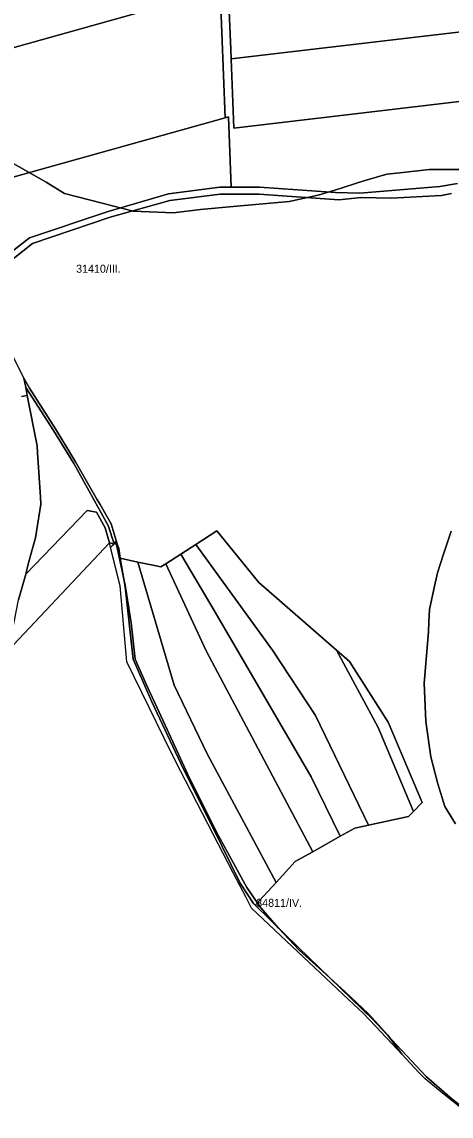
# Model space of a CAD drawing. Extents: x -541351 to -537540, y -1162694 to -1159725.
# Drawn here: x -539137 to -538870, y -1162618 to -1161934 of the extents above; entities that cross this region are included whole.
import ezdxf

# ---------------------------------------------------------------- set-up
doc = ezdxf.new("R2010")
doc.units = 0
for name, color, linetype in [('95560013', 7, 'Continuous'), ('95640013', 7, 'Continuous'), ('95660013', 7, 'Continuous')]:
    doc.layers.add(name, color=color, linetype=linetype)

msp = doc.modelspace()

# ---------------------------------------------------------------- linework, layer by layer
at = {"layer": '95560013'}
for points in [[(-539212.32, -1161913.69), (-539214.84, -1161903.7), (-539217.45, -1161893.33), (-539017.01, -1161837.1), (-539013.85, -1161913.55), (-539200.6, -1161966.02), (-539206.22, -1161940.94)], [(-539007.14, -1161951.05), (-539008.79, -1161912.59), (-538817.52, -1161890.24), (-538820.83, -1161934.92), (-539006.92, -1161956.95)], [(-539197.76, -1161978.7), (-539200.6, -1161966.02), (-539013.85, -1161913.55), (-539010.53, -1161993.75), (-539184.9, -1162042.56), (-539186.67, -1162034.94), (-539187.18, -1162032.19), (-539193.59, -1161997.34)], [(-538820.83, -1161934.92), (-538824.09, -1161978.8), (-539005.3, -1162000.22), (-539006.92, -1161956.95)], [(-539083.65, -1162052.18), (-539132.72, -1162068.62), (-539167.17, -1162095.62), (-539177.1, -1162076.06), (-539179.07, -1162067.59), (-539184.9, -1162042.56), (-539010.53, -1161993.75), (-539008.56, -1161993.2), (-539006.92, -1162037.12), (-539013.92, -1162037.13), (-539045.95, -1162041.27)], [(-539128.98, -1162256.1), (-539125.58, -1162235.11), (-539125.86, -1162230.82), (-539127.7, -1162203.08), (-539127.98, -1162198.77), (-539134.14, -1162167.31), (-539135.1, -1162162.18), (-539117.68, -1162189.14), (-539105.17, -1162209.73), (-539083.56, -1162248.52), (-539080, -1162259.98), (-539082.83, -1162259.23), (-539085.53, -1162249.94), (-539091, -1162240.09), (-539096.84, -1162239.12), (-539135.12, -1162278.84), (-539133.55, -1162272.74), (-539131.26, -1162264.39)], [(-539139.62, -1162294.87), (-539135.12, -1162278.84), (-539096.84, -1162239.12), (-539091, -1162240.09), (-539085.53, -1162249.94), (-539082.83, -1162259.23), (-539142.64, -1162323.16), (-539145.63, -1162326.35), (-539145.6, -1162326.2)], [(-538921.23, -1162435.74), (-538954.32, -1162367.32), (-538981.04, -1162326.43), (-539028.88, -1162260.3), (-539015.79, -1162251.87), (-538989.69, -1162284.09), (-538941.12, -1162326.35), (-538915.25, -1162374.75), (-538893.18, -1162427.24), (-538896.24, -1162430.37)], [(-538929.69, -1162437.56), (-538938.83, -1162442.7), (-538956.93, -1162405.55), (-539016.81, -1162302.57), (-539038.32, -1162266.38), (-539028.88, -1162260.3), (-538981.04, -1162326.43), (-538954.32, -1162367.32), (-538921.23, -1162435.74)], [(-539056.46, -1162358.75), (-539068.09, -1162332.03), (-539073.03, -1162286.84), (-539076.06, -1162268.99), (-539065.09, -1162271.35), (-539042.53, -1162348.19), (-539021.89, -1162391.27), (-538978.82, -1162471.52), (-538991.83, -1162485.79), (-538992.91, -1162484.72), (-539001.22, -1162471.94), (-539018.06, -1162437.54), (-539036.61, -1162400.8)], [(-538956.01, -1162452.36), (-538965.48, -1162457.69), (-538966.96, -1162458.52), (-538978.82, -1162471.52), (-539021.89, -1162391.27), (-539042.53, -1162348.19), (-539065.09, -1162271.35), (-539053.73, -1162273.79), (-539050.8, -1162274.41), (-539047.58, -1162272.35), (-539022.54, -1162326.91)], [(-539016.81, -1162302.57), (-538956.93, -1162405.55), (-538938.83, -1162442.7), (-538956.01, -1162452.36), (-539022.54, -1162326.91), (-539047.58, -1162272.35), (-539038.32, -1162266.38)], [(-538941.12, -1162326.35), (-538932.97, -1162333.44), (-538908.81, -1162371.47), (-538887.63, -1162421.53), (-538893.18, -1162427.24), (-538915.25, -1162374.75)]]:
    msp.add_lwpolyline(points, close=True, dxfattribs=at)
for points in [[(-538865.57, -1162034.76), (-538876.72, -1162036.74), (-538926.62, -1162040.85), (-538941.77, -1162040.48), (-538989.17, -1162037.11), (-539003.92, -1162037.12), (-539006.92, -1162037.12), (-539008.56, -1161993.2), (-539010.53, -1161993.75), (-539013.85, -1161913.55)], [(-539008.79, -1161912.59), (-539007.14, -1161951.05), (-539006.92, -1161956.95), (-539005.3, -1162000.22), (-538824.09, -1161978.8)], [(-539165.27, -1162099.36), (-539130.8, -1162072.28), (-539082.49, -1162055.78), (-539045.11, -1162045.4), (-539013.66, -1162041.4), (-538989.46, -1162041.38), (-538939.77, -1162044.97), (-538925.8, -1162043.6), (-538907.04, -1162043.97), (-538875.54, -1162042.25), (-538869.43, -1162041.03)], [(-538855.65, -1162617.58), (-538870.45, -1162605.67), (-538885.13, -1162592.83), (-538918.63, -1162556.93), (-538964.98, -1162512.08), (-538991.83, -1162485.79), (-538978.82, -1162471.52), (-538966.96, -1162458.52), (-538965.48, -1162457.69), (-538956.01, -1162452.36), (-538938.83, -1162442.7), (-538929.69, -1162437.56), (-538921.23, -1162435.74), (-538896.24, -1162430.37), (-538893.18, -1162427.24), (-538887.63, -1162421.53), (-538908.81, -1162371.47), (-538932.97, -1162333.44), (-538941.12, -1162326.35), (-538989.69, -1162284.09), (-539015.79, -1162251.87), (-539028.88, -1162260.3), (-539038.32, -1162266.38), (-539047.58, -1162272.35), (-539050.8, -1162274.41), (-539053.73, -1162273.79), (-539065.09, -1162271.35), (-539076.06, -1162268.99), (-539077.08, -1162262.94), (-539077.99, -1162260.02), (-539081.84, -1162247.4), (-539088.7, -1162235.39), (-539090.65, -1162231.98), (-539103.97, -1162208.68), (-539116.44, -1162188.05), (-539132.79, -1162162.66), (-539136.3, -1162156.43), (-539142.82, -1162143.59)]]:
    msp.add_lwpolyline(points, dxfattribs=at)
at = {"layer": '95640013'}
for points in [[(-538869.43, -1162041.03), (-538875.54, -1162042.25), (-538907.04, -1162043.97), (-538925.8, -1162043.6), (-538939.77, -1162044.97), (-538989.46, -1162041.38), (-539013.66, -1162041.4), (-539045.11, -1162045.4), (-539082.49, -1162055.78), (-539130.8, -1162072.28), (-539165.27, -1162099.36), (-539167.17, -1162095.62), (-539132.72, -1162068.62), (-539083.65, -1162052.18), (-539045.95, -1162041.27), (-539013.92, -1162037.13), (-539006.92, -1162037.12), (-539003.92, -1162037.12), (-538989.17, -1162037.11), (-538941.77, -1162040.48), (-538926.62, -1162040.85), (-538876.72, -1162036.74), (-538865.57, -1162034.76)], [(-539142.82, -1162143.59), (-539136.3, -1162156.43), (-539135.1, -1162162.18), (-539134.14, -1162167.31), (-539137.66, -1162167.95)], [(-539137.66, -1162167.95), (-539134.14, -1162167.31), (-539127.98, -1162198.77), (-539127.7, -1162203.08), (-539125.86, -1162230.82), (-539125.58, -1162235.11), (-539128.98, -1162256.1), (-539131.26, -1162264.39), (-539133.55, -1162272.74), (-539135.12, -1162278.84), (-539139.62, -1162294.87)], [(-538862.99, -1162612.9), (-538874.92, -1162603.19), (-538885.86, -1162594.28), (-538889.69, -1162590.22), (-538903.28, -1162575.82), (-538916.9, -1162561.39), (-538924.5, -1162553.34), (-538927.27, -1162550.73), (-538937.03, -1162541.53), (-538979.54, -1162501.45), (-538994.17, -1162487.65), (-538997.62, -1162480.98), (-539005.64, -1162465.5), (-539015.03, -1162447.36), (-539024.84, -1162428.38), (-539035.48, -1162407.82), (-539038.4, -1162402.18), (-539044.02, -1162390.7), (-539071.91, -1162333.79), (-539076.15, -1162286.28), (-539082.83, -1162259.23), (-539080, -1162259.98), (-539077.99, -1162260.02), (-539077.08, -1162262.94), (-539076.06, -1162268.99), (-539073.03, -1162286.84), (-539068.09, -1162332.03), (-539056.46, -1162358.75), (-539036.61, -1162400.8), (-539018.06, -1162437.54), (-539001.22, -1162471.94), (-538992.91, -1162484.72), (-538991.83, -1162485.79), (-538964.98, -1162512.08), (-538918.63, -1162556.93), (-538885.13, -1162592.83), (-538870.45, -1162605.67), (-538855.65, -1162617.58)]]:
    msp.add_lwpolyline(points, dxfattribs=at)
msp.add_lwpolyline([(-539136.3, -1162156.43), (-539132.79, -1162162.66), (-539116.44, -1162188.05), (-539103.97, -1162208.68), (-539090.65, -1162231.98), (-539088.7, -1162235.39), (-539081.84, -1162247.4), (-539077.99, -1162260.02), (-539080, -1162259.98), (-539083.56, -1162248.52), (-539105.17, -1162209.73), (-539117.68, -1162189.14), (-539135.1, -1162162.18)], close=True, dxfattribs=at)
at = {"layer": '95660013'}
for points in [[(-538849.37, -1162026), (-538883.31, -1162026), (-538901.69, -1162028), (-538909.81, -1162029), (-538924.12, -1162033), (-538942.12, -1162039), (-538952.69, -1162042), (-538970.62, -1162046), (-539003.31, -1162049), (-539026, -1162051), (-539042.81, -1162053), (-539068, -1162052), (-539087.37, -1162047), (-539110.81, -1162041), (-539122.37, -1162034), (-539146.81, -1162020), (-539161.87, -1162007), (-539166.31, -1162000), (-539179.62, -1161966), (-539195.31, -1161920)], [(-539195.31, -1161920), (-539179.62, -1161966), (-539166.31, -1162000), (-539161.87, -1162007), (-539146.81, -1162020), (-539122.37, -1162034), (-539110.81, -1162041), (-539087.37, -1162047), (-539068, -1162052), (-539042.81, -1162053), (-539026, -1162051), (-539003.31, -1162049), (-538970.62, -1162046), (-538952.69, -1162042), (-538942.12, -1162039), (-538924.12, -1162033), (-538909.81, -1162029), (-538901.69, -1162028), (-538883.31, -1162026), (-538849.37, -1162026)], [(-538866.81, -1162435), (-538873.5, -1162424), (-538877.87, -1162410), (-538882.31, -1162393), (-538885.37, -1162371), (-538886.5, -1162347), (-538883.69, -1162315), (-538883.44, -1162308.78), (-538883.12, -1162301), (-538880.38, -1162288.22), (-538878.19, -1162278), (-538874.38, -1162266.44), (-538869.62, -1162252)], [(-538869.62, -1162252), (-538874.38, -1162266.44), (-538878.19, -1162278), (-538880.38, -1162288.22), (-538883.12, -1162301), (-538883.44, -1162308.78), (-538883.69, -1162315), (-538886.5, -1162347), (-538885.37, -1162371), (-538882.31, -1162393), (-538877.87, -1162410), (-538873.5, -1162424), (-538866.81, -1162435)], [(-538862.99, -1162612.9), (-538874.92, -1162603.19), (-538885.86, -1162594.28), (-538889.69, -1162590.22), (-538900.42, -1162578.85), (-538909.05, -1162566.98), (-538921.18, -1162553.62), (-538935.8, -1162539.98), (-538949.84, -1162527.04), (-538964.37, -1162513.81), (-538977.37, -1162500.12), (-538988.32, -1162487.46), (-538997.13, -1162474.77), (-539014.94, -1162441.97), (-539033.92, -1162404.18), (-539048.17, -1162373.22), (-539059.88, -1162347.62), (-539066.83, -1162331.98), (-539069.27, -1162309.34), (-539072.95, -1162285.74), (-539078.86, -1162258.5), (-539081.02, -1162260.99), (-539081.75, -1162261.77), (-539082.11, -1162262.15), (-539082.83, -1162259.23), (-539142.64, -1162323.16)]]:
    msp.add_lwpolyline(points, dxfattribs=at)
msp.add_lwpolyline([(-538909.05, -1162566.98), (-538900.42, -1162578.85), (-538903.28, -1162575.82), (-538916.9, -1162561.39), (-538924.5, -1162553.34), (-538927.27, -1162550.73), (-538937.03, -1162541.53), (-538979.54, -1162501.45), (-538994.17, -1162487.65), (-538997.62, -1162480.98), (-539005.64, -1162465.5), (-539015.03, -1162447.36), (-539024.84, -1162428.38), (-539035.48, -1162407.82), (-539038.4, -1162402.18), (-539044.02, -1162390.7), (-539071.91, -1162333.79), (-539076.15, -1162286.28), (-539082.11, -1162262.15), (-539081.75, -1162261.77), (-539081.02, -1162260.99), (-539078.86, -1162258.5), (-539072.95, -1162285.74), (-539069.27, -1162309.34), (-539066.83, -1162331.98), (-539059.88, -1162347.62), (-539048.17, -1162373.22), (-539033.92, -1162404.18), (-539014.94, -1162441.97), (-538997.13, -1162474.77), (-538988.32, -1162487.46), (-538977.37, -1162500.12), (-538964.37, -1162513.81), (-538949.84, -1162527.04), (-538935.8, -1162539.98), (-538921.18, -1162553.62)], close=True, dxfattribs=at)

# ---------------------------------------------------------------- texts
for s, rotation, p in [('31410/III.', 360, (-539103.65, -1162090.53)), ('34811/IV.', 0, (-538991.27, -1162486.8))]:
    msp.add_text(s, height=5, rotation=rotation, dxfattribs=at).set_placement(p)

doc.saveas('drawing.dxf')
